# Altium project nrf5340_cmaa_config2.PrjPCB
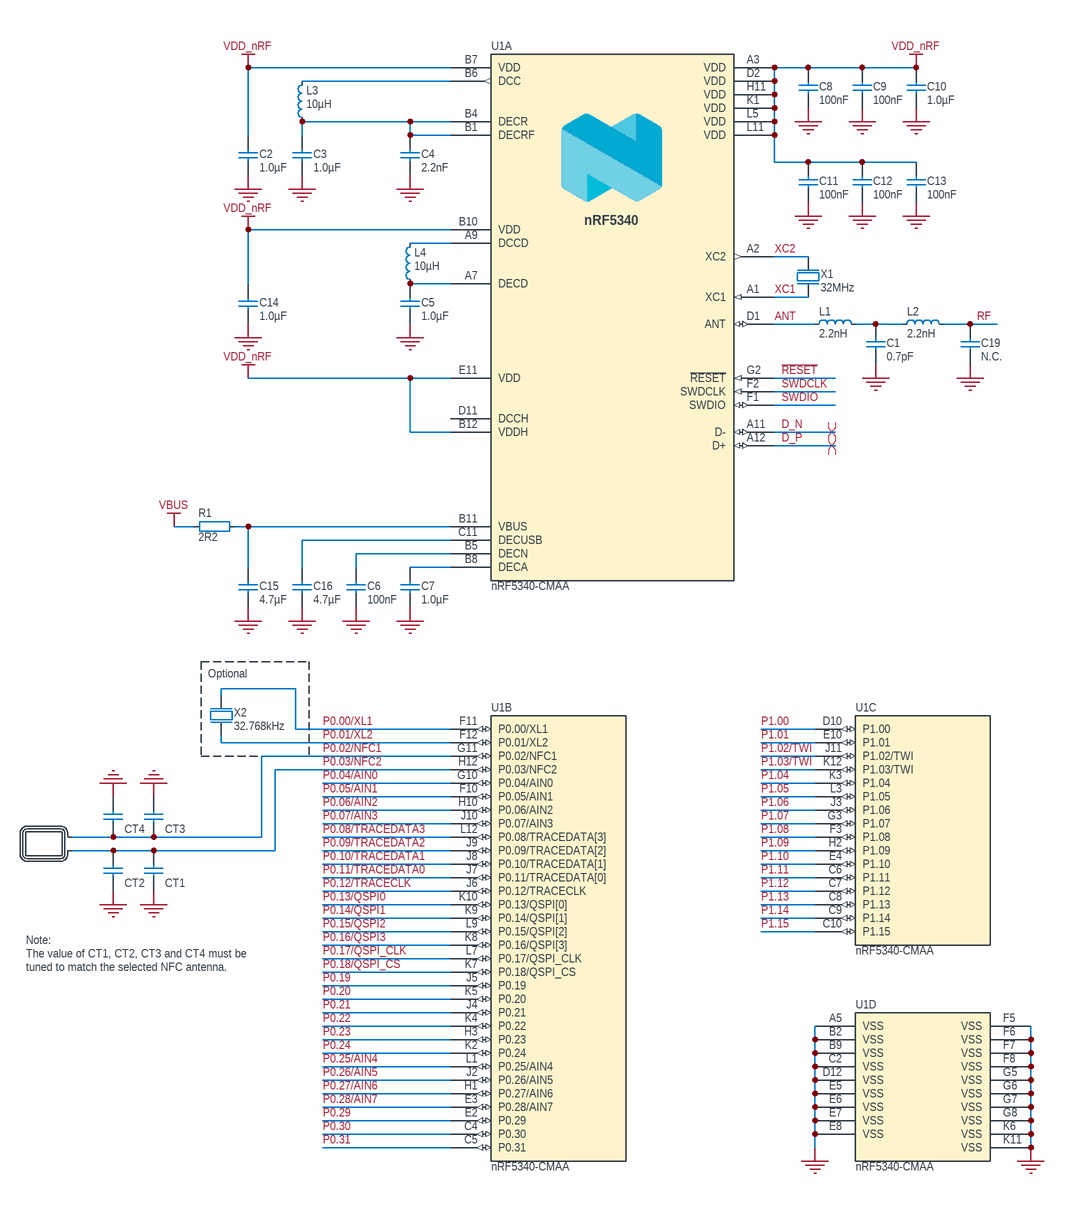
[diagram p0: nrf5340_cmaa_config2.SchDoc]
1 sheet, 30 parts. Net scope: global (net labels, ports and power ports of the same name join across sheets).
Board file: nrf5340_cmaa_config2.PcbDoc

## Sheet nrf5340_cmaa_config2.SchDoc
size A3; Organization: Nordic Semiconductor; DocumentNumber: 1; Revision: 1.0; SheetNumber: 1; SheetTotal: 1; DrawnBy: RUBR; DocumentSize: A3; RefLayoutTitle: Reference Layout Config. 2: VDD supply, DCDC, USB, NFC; Device: nRF5340-CMAA; Classification: PUBLIC

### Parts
A1  NFC Antenna  [TP_2x1mm_TH]  (value not drawn)  (no BOM)
C1  0.7pF  [CAPC0603X03L_C]
C2  1.0µF  [CAPC1005X04L]
C3  1.0µF  [CAPC1005X04L]
C4  2.2nF  [CAPC0603X03L_C]
C5  1.0µF  [CAPC1005X04L]
C6  100nF  [CAPC0603X03L_C]
C7  1.0µF  [CAPC1005X04L]
C8  100nF  [CAPC0603X03L_C]
C9  100nF  [CAPC0603X03L_C]
C10  1.0µF  [CAPC1005X04L]
C11  100nF  [CAPC0603X03L_C]
C12  100nF  [CAPC0603X03L_C]
C13  100nF  [CAPC0603X03L_C]
C14  1.0µF  [CAPC1005X04L]
C15  4.7µF  [CAPC1608X06L]
C16  4.7µF  [CAPC1608X06L]
C19  N.C.  [CAPC0603X03L_C_NC]
CT1  Antenna dependent  [CAPC0603X03L_C]  (value not drawn)
CT2  Antenna dependent  [CAPC0603X03L_C]  (value not drawn)
CT3  Antenna dependent  [CAPC0603X03L_C]  (value not drawn)
CT4  Antenna dependent  [CAPC0603X03L_C]  (value not drawn)
L1  2.2nH  [INDC0603X03L_C]
L2  2.2nH  [INDC0603X03L_C]
L3  10µH  [INDC1608X06L]
L4  10µH  [INDC1608X06L]
R1  2R2  [RESC0603X03L_C]
U1  nRF5340-CMAA  [BGA95C35P12X11_439X399X49]  (parts A,B,C,D of 4)
X1  32MHz  [BT-XTAL_2016]
X2  32.768kHz  [XTAL_2012]

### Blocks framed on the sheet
Optional: X2

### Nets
GND: C1.1 C2.2 C3.1 C4.2 C5.1 C6.2 C7.1 C8.2 C9.2 C10.2 C11.2 C12.2 C13.2 C14.1 C15.2 C16.2 C19.1 CT1.2 CT2.2 CT3.1 CT4.1 U1.A5(VSS) U1.B2(VSS) U1.B9(VSS) U1.C2(VSS) U1.D12(VSS) U1.E5(VSS) U1.E6(VSS) U1.E7(VSS) U1.E8(VSS) U1.F5(VSS) U1.F6(VSS) U1.F7(VSS) U1.F8(VSS) U1.G5(VSS) U1.G6(VSS) U1.G7(VSS) U1.G8(VSS) U1.K6(VSS) U1.K11(VSS) X1.2(GND) X1.4(GND)
VBUS: R1.1
VDD_nRF: C2.1 C8.1 C9.1 C10.1 C11.1 C12.1 C13.1 C14.2 U1.A3(VDD) U1.B7(VDD) U1.B10(VDD) U1.B12(VDDH) U1.D2(VDD) U1.E11(VDD) U1.H11(VDD) U1.K1(VDD) U1.L5(VDD) U1.L11(VDD)
ANT: L1.2 U1.D1(ANT)
D_N: U1.A11(D-)
D_P: U1.A12(D+)
P0.00/XL1: U1.F11(P0.00/XL1) X2.1(inp)
P0.01/XL2: U1.F12(P0.01/XL2) X2.2(out)
P0.02/NFC1: A1.1 CT3.2 CT4.2 U1.G11(P0.02/NFC1)
P0.03/NFC2: A1.2 CT1.1 CT2.1 U1.H12(P0.03/NFC2)
P0.04/AIN0: U1.G10(P0.04/AIN0)
P0.05/AIN1: U1.F10(P0.05/AIN1)
P0.06/AIN2: U1.H10(P0.06/AIN2)
P0.07/AIN3: U1.J10(P0.07/AIN3)
P0.08/TRACEDATA3: U1.L12(P0.08/TRACEDATA[3])
P0.09/TRACEDATA2: U1.J9(P0.09/TRACEDATA[2])
P0.10/TRACEDATA1: U1.J8(P0.10/TRACEDATA[1])
P0.11/TRACEDATA0: U1.J7(P0.11/TRACEDATA[0])
P0.12/TRACECLK: U1.J6(P0.12/TRACECLK)
P0.13/QSPI0: U1.K10(P0.13/QSPI[0])
P0.14/QSPI1: U1.K9(P0.14/QSPI[1])
P0.15/QSPI2: U1.L9(P0.15/QSPI[2])
P0.16/QSPI3: U1.K8(P0.16/QSPI[3])
P0.17/QSPI_CLK: U1.L7(P0.17/QSPI_CLK)
P0.18/QSPI_CS: U1.K7(P0.18/QSPI_CS)
P0.19: U1.J5(P0.19)
P0.20: U1.K5(P0.20)
P0.21: U1.J4(P0.21)
P0.22: U1.K4(P0.22)
P0.23: U1.H3(P0.23)
P0.24: U1.K2(P0.24)
P0.25/AIN4: U1.L1(P0.25/AIN4)
P0.26/AIN5: U1.J2(P0.26/AIN5)
P0.27/AIN6: U1.H1(P0.27/AIN6)
P0.28/AIN7: U1.E3(P0.28/AIN7)
P0.29: U1.E2(P0.29)
P0.30: U1.C4(P0.30)
P0.31: U1.C5(P0.31)
P1.00: U1.D10(P1.00)
P1.01: U1.E10(P1.01)
P1.02/TWI: U1.J11(P1.02/TWI)
P1.03/TWI: U1.K12(P1.03/TWI)
P1.04: U1.K3(P1.04)
P1.05: U1.L3(P1.05)
P1.06: U1.J3(P1.06)
P1.07: U1.G3(P1.07)
P1.08: U1.F3(P1.08)
P1.09: U1.H2(P1.09)
P1.10: U1.E4(P1.10)
P1.11: U1.C6(P1.11)
P1.12: U1.C7(P1.12)
P1.13: U1.C8(P1.13)
P1.14: U1.C9(P1.14)
P1.15: U1.C10(P1.15)
~{RESET}: U1.G2(~{RESET})
RF: C19.2 L2.1
SWDCLK: U1.F2(SWDCLK)
SWDIO: U1.F1(SWDIO)
XC1: U1.A1(XC1) X1.1(inp)
XC2: U1.A2(XC2) X1.3(out)
NetC1_2: C1.2 L1.1 L2.2
NetC3_2: C3.2 C4.1 L3.1 U1.B1(DECRF) U1.B4(DECR)
NetC5_2: C5.2 L4.1 U1.A7(DECD)
NetC6_1: C6.1 U1.B5(DECN)
NetC7_2: C7.2 U1.B8(DECA)
NetC15_1: C15.1 R1.2 U1.B11(VBUS)
NetC16_1: C16.1 U1.C11(DECUSB)
NetL3_2: L3.2 U1.B6(DCC)
NetL4_2: L4.2 U1.A9(DCCD)

Not connected (* = marked no-connect by the designer): U1 D11(DCCH)

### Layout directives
differential pair: D_N, D_P

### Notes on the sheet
- Note:
  The value of CT1, CT2, CT3 and CT4 must be tuned to match the selected NFC antenna.

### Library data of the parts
A1 = NFC_ANT_TP: Pad Count: 2
C1 = C0201-0.7p: Capacitor, NP0, ±0.05pF; Pad Count: 2
C2 C3 C5 C7 C10 C14 = C0402-1µ0-10V-X7S-GRM155C71A105KE11: Capacitor, X7S, ±10%; Pad Count: 2
C4 = C0201-2n2: Capacitor, X7R, ±10%; Pad Count: 2
C6 C8 C9 C11-C13 = C0201-100n-16V-X7S: Capacitor, X7S, ±10%; Pad Count: 2
C15 = C0603-4µ7-10V-X7S: Capacitor, X7S, ±10%; Pad Count: 2
C16 = C0603-4µ7-6.3V-X7R: Capacitor, X7R, ±10%; Pad Count: 2
C19 = C0201-N.C.: Not mounted; Assembly: Not mounted; Pad Count: 2
CT1-CT4 = C0201-TBD: Capacitor, NP0, ±5%; Pad Count: 2
L1 L2 = L0201-2n2: High frequency chip inductor, ±5%; Pad Count: 2
L3 L4 = L0603-10µ: Chip inductor, IDC,min = 50 mA, ±20%; Pad Count: 2
R1 = R0201-2R2: Resistor, ±1%, 0.05W; Pad Count: 2
U1 = nRF5340-CMAA: Multi-protocol Bluetooth Low Energy, IEEE 802.15.4, ANT and 2.4GHz proprietary system-on-chip; Manufacturer: Nordic Semiconductor; Pad Count: 95
X1 = XTAL_SMD2016_32MHz_8pF_General: XTAL SMD 2016, 32MHz, Cl=8pF, Total Tol: ±30ppm; Pad Count: 4
X2 = XTAL_SMD2012_32.768kHz_9pF_General: XTAL SMD 2012, 32.768kHz, Cl=9pF, Total Tol: ±50ppm; Pad Count: 2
